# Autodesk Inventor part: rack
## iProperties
Author: Elise Moss
Created: 2001-09
Part Number: rack
Document SubType Name: Modeling
Designer: Elise Moss
Control State: 0
Master: False
Checked Out: False
PropertySet Name: Design Tracking Control
Shininess: 64.0
Angle Display Precision: 2
Document Length Units: 11272
Document Angle Units: 11286
Document Time Units: 11279
Document Mass Units: 11290
Document Length Units Precision: 3
Document Angle Units Precision: 2
Compacted: True
PropertySet Name: _Private Model Information
Density: 0.0
Volumn: 0.0
Area: 0.0
PropertySet Name: Model Information
